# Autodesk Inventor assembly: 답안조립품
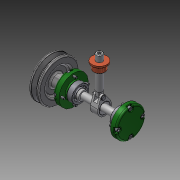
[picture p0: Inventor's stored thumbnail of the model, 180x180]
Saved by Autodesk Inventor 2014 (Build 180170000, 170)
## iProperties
Created: 2016-02
Part Number: 답안조립품
Document SubType Name: Assembly
Designer: D.Y.KIM
Author: D.Y.KIM
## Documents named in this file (15)
- C:\Users\Administrator\Desktop\460211V1029\답안조립품.iam
- C:\Users\Administrator\Desktop\460211V1029\1-본체.ipt
- C:\Users\Administrator\Desktop\460211V1029\뒤커버.ipt
- C:\Users\Administrator\Desktop\460211V1029\앞커버.ipt
- C:\Users\Administrator\Desktop\460211V1029\베어링 12 x 32 x 10.ipt
- C:\Users\Administrator\Desktop\460211V1029\편심축.ipt
- C:\Users\Administrator\Desktop\460211V1029\오일실 12 25 7.ipt
- C:\Users\Administrator\Desktop\460211V1029\키 4 x 4 x 10.ipt
- C:\Users\Administrator\Desktop\460211V1029\링크.ipt
- C:\Users\Administrator\Desktop\460211V1029\핀 5 x 18.ipt
- C:\Users\Administrator\Desktop\460211V1029\슬라이드.ipt
- C:\Users\Administrator\Desktop\460211V1029\부시.ipt
- C:\Users\Administrator\Desktop\460211V1029\V벨트풀리.ipt
- C:\Users\Administrator\Desktop\460211V1029\멈춤나사 M3x8.ipt
- C:\Users\Administrator\Desktop\460211V1029\볼트 M4 x 12.ipt
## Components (11 placed, 4 different names)
1. 1-본체:1 — 각도:1, 각도:2, 각도:3
2. 핀 5 x 18:1
3. V벨트풀리:1 — 플러쉬:2
4. ISO 4762 M4 x 12:1 — 각도:3
5. ISO 4762 M4 x 12:3
6. ISO 4762 M4 x 12:4
7. ISO 4762 M4 x 12:5
8. ISO 4762 M4 x 12:2 — 각도:2
9. ISO 4762 M4 x 12:6
10. ISO 4762 M4 x 12:7
11. ISO 4762 M4 x 12:8
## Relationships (4: Angle 3, Flush 1)
- 플러쉬:2 [Flush]: V벨트풀리:1
- 각도:1 [Angle]: 1-본체:1
- 각도:2 [Angle]: 1-본체:1 ↔ ISO 4762 M4 x 12:2
- 각도:3 [Angle]: 1-본체:1 ↔ ISO 4762 M4 x 12:1
